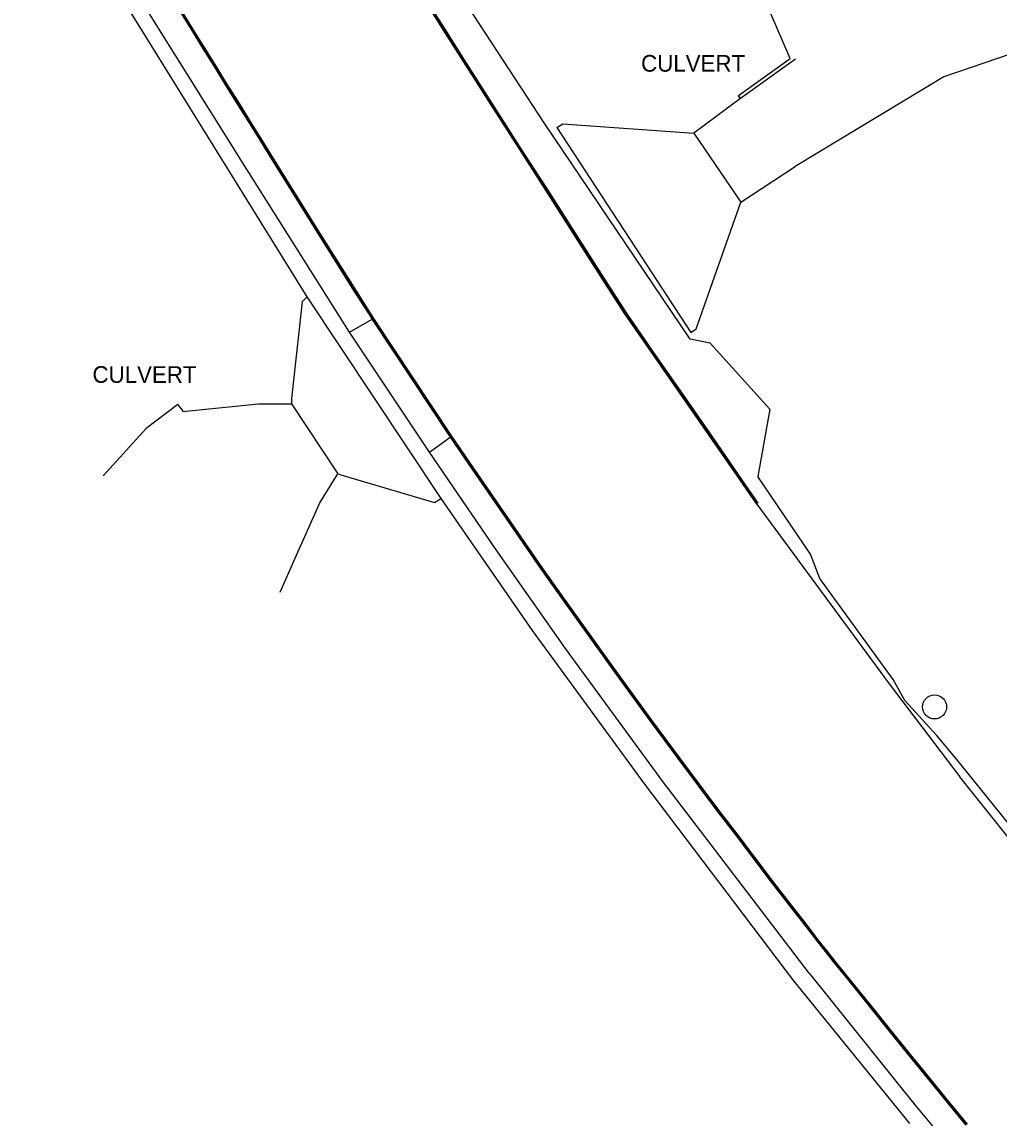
# Model space of a CAD drawing. Extents: x 368532 to 392481, y 10654822 to 10676899.
# Drawn here: x 374280.6 to 374573.7, y 10671119.3 to 10671447.9 of the extents above; entities that cross this region are included whole.
import ezdxf

# ---------------------------------------------------------------- set-up
doc = ezdxf.new("R2010")
doc.units = 0
for name, color, linetype in [('p_drainage conc drain', 7, 'Continuous'), ('p_drainage culvert', 7, 'Continuous'), ('p_dtm retaining wall', 7, 'Continuous'), ('p_dtm sidewalk', 7, 'Continuous'), ('p_road - paved curb', 7, 'Continuous'), ('p_structure constr area', 7, 'Continuous'), ('p_structure unidentified', 7, 'Continuous')]:
    doc.layers.add(name, color=color, linetype=linetype)

msp = doc.modelspace()

# ---------------------------------------------------------------- linework, layer by layer
at = {"layer": 'p_drainage conc drain'}
for p, q in [((374511, 10671437), (374496.77, 10671470.21)), ((374495.56, 10671425.88), (374511, 10671437)), ((374496.16, 10671424.98), (374495.56, 10671425.88)), ((374441.02, 10671416.31), (374442.85, 10671417.39)), ((374441.02, 10671416.31), (374481.21, 10671354.82)), ((374442.85, 10671417.39), (374482.18, 10671414.62)), ((374482.8, 10671355.94), (374496.24, 10671393.91)), ((374366.22, 10671365.53), (374364.67, 10671364.01)), ((374364.67, 10671364.01), (374361.52, 10671334.99)), ((374378.91, 10671354.92), (374385.62, 10671358.77)), ((374481.21, 10671354.82), (374482.8, 10671355.94)), ((374327.37, 10671333.18), (374317.93, 10671326.05)), ((374328.97, 10671331.27), (374327.37, 10671333.18)), ((374361.52, 10671334.99), (374361.45, 10671333.41)), ((374317.93, 10671326.05), (374304.99, 10671311.88)), ((374402.88, 10671318.95), (374409.07, 10671323.42)), ((374376.41, 10671312.02), (374375.36, 10671312.47)), ((374404.49, 10671303.69), (374376.41, 10671312.02)), ((374406.32, 10671305.01), (374404.49, 10671303.69))]:
    msp.add_line(p, q, dxfattribs=at)
at = {"layer": 'p_drainage culvert'}
for p, q in [((374496.16, 10671424.98), (374482.18, 10671414.62)), ((374482.18, 10671414.62), (374496.24, 10671393.91)), ((374496.24, 10671393.91), (374512.57, 10671404.53)), ((374328.78, 10671331.09), (374351.61, 10671333.41)), ((374351.61, 10671333.41), (374361.45, 10671333.41)), ((374361.45, 10671333.41), (374375.36, 10671312.47)), ((374369.92, 10671303.71), (374375.36, 10671312.47)), ((374362.57, 10671287.15), (374369.92, 10671303.71)), ((374358.03, 10671276.92), (374362.57, 10671287.15))]:
    msp.add_line(p, q, dxfattribs=at)
at = {"layer": 'p_dtm retaining wall'}
for p, q in [((374587.05, 10671441.71), (374557.11, 10671431.44)), ((374512.58, 10671436.71), (374496.16, 10671424.98)), ((374557.11, 10671431.44), (374512.57, 10671404.53))]:
    msp.add_line(p, q, dxfattribs=at)
at = {"layer": 'p_dtm sidewalk'}
for p, q in [((374316.79, 10671445.13), (374280.62, 10671503.52)), ((374347.52, 10671404.64), (374307.73, 10671468.42)), ((374366.22, 10671365.53), (374316.79, 10671445.13)), ((374378.91, 10671354.92), (374347.52, 10671404.64)), ((374406.32, 10671305.01), (374366.22, 10671365.53)), ((374402.88, 10671318.95), (374378.91, 10671354.92)), ((374422.66, 10671289.99), (374402.88, 10671318.95)), ((374433.78, 10671265.48), (374406.32, 10671305.01)), ((374443.66, 10671260.05), (374422.66, 10671289.99)), ((374467.47, 10671219.43), (374433.78, 10671265.48)), ((374472.79, 10671220.21), (374443.66, 10671260.05)), ((374512.09, 10671160.44), (374467.47, 10671219.43)), ((374516.71, 10671162.71), (374472.79, 10671220.21)), ((374516.71, 10671162.71), (374548.41, 10671123.22)), ((374546.87, 10671117.68), (374512.09, 10671160.44)), ((374548.41, 10671123.22), (374571.96, 10671095.17))]:
    msp.add_line(p, q, dxfattribs=at)
at = {"layer": 'p_road - paved curb'}
for p, q in [((374407.1, 10671445.46), (374402.27, 10671453.12)), ((374407.23, 10671445.54), (374402.4, 10671453.2)), ((374407.52, 10671445.73), (374402.69, 10671453.39)), ((374328.45, 10671450.3), (374331.88, 10671444.82)), ((374328.74, 10671450.48), (374332.17, 10671445)), ((374331.88, 10671444.82), (374334.81, 10671440.03)), ((374332.17, 10671445), (374335.11, 10671440.21)), ((374413.03, 10671436.08), (374407.1, 10671445.46)), ((374413.16, 10671436.16), (374407.23, 10671445.54)), ((374413.45, 10671436.35), (374407.52, 10671445.73)), ((374334.81, 10671440.03), (374338.03, 10671434.9)), ((374335.11, 10671440.21), (374338.32, 10671435.08)), ((374338.03, 10671434.9), (374341.5, 10671429.31)), ((374338.32, 10671435.08), (374341.79, 10671429.49)), ((374421.13, 10671423.41), (374413.03, 10671436.08)), ((374421.26, 10671423.49), (374413.16, 10671436.16)), ((374421.55, 10671423.68), (374413.45, 10671436.35)), ((374341.5, 10671429.31), (374344.81, 10671423.97)), ((374341.79, 10671429.49), (374345.1, 10671424.15)), ((374344.81, 10671423.97), (374348.34, 10671418.28)), ((374345.1, 10671424.15), (374348.63, 10671418.46)), ((374430.66, 10671408.54), (374421.13, 10671423.41)), ((374430.79, 10671408.62), (374421.26, 10671423.49)), ((374431.08, 10671408.81), (374421.55, 10671423.68)), ((374348.34, 10671418.28), (374351.85, 10671412.67)), ((374348.63, 10671418.46), (374352.14, 10671412.85)), ((374351.85, 10671412.67), (374354.7, 10671408.04)), ((374352.14, 10671412.85), (374355, 10671408.22)), ((374354.7, 10671408.04), (374369.02, 10671385)), ((374355, 10671408.22), (374369.31, 10671385.19)), ((374437.79, 10671397.46), (374430.66, 10671408.54)), ((374437.92, 10671397.54), (374430.79, 10671408.62)), ((374438.21, 10671397.73), (374431.08, 10671408.81)), ((374445.98, 10671384.57), (374437.79, 10671397.46)), ((374446.11, 10671384.65), (374437.92, 10671397.54)), ((374446.4, 10671384.84), (374438.21, 10671397.73)), ((374369.02, 10671385), (374380.5, 10671366.83)), ((374369.31, 10671385.19), (374380.79, 10671367.02)), ((374454.79, 10671370.83), (374445.98, 10671384.57)), ((374454.92, 10671370.91), (374446.11, 10671384.65)), ((374455.21, 10671371.1), (374446.4, 10671384.84)), ((374461.47, 10671360.41), (374454.79, 10671370.83)), ((374461.59, 10671360.49), (374454.92, 10671370.91)), ((374461.89, 10671360.69), (374455.21, 10671371.1)), ((374380.5, 10671366.83), (374385.62, 10671358.77)), ((374380.79, 10671367.02), (374385.93, 10671358.93)), ((374385.62, 10671358.77), (374385.64, 10671358.74)), ((374385.64, 10671358.74), (374409.07, 10671323.42)), ((374385.93, 10671358.93), (374409.37, 10671323.62)), ((374469.45, 10671348.89), (374461.47, 10671360.41)), ((374469.57, 10671348.98), (374461.59, 10671360.49)), ((374469.86, 10671349.17), (374461.89, 10671360.69)), ((374479.18, 10671334.88), (374469.45, 10671348.89)), ((374479.3, 10671334.97), (374469.57, 10671348.98)), ((374479.59, 10671335.17), (374469.86, 10671349.17)), ((374487.57, 10671322.79), (374479.18, 10671334.88)), ((374487.69, 10671322.88), (374479.3, 10671334.97)), ((374487.98, 10671323.08), (374479.59, 10671335.17)), ((374409.07, 10671323.42), (374409.08, 10671323.42)), ((374409.08, 10671323.42), (374415.78, 10671313.62)), ((374409.37, 10671323.62), (374416.07, 10671313.82)), ((374495.04, 10671312.03), (374487.57, 10671322.79)), ((374495.16, 10671312.12), (374487.69, 10671322.88)), ((374495.45, 10671312.32), (374487.98, 10671323.08)), ((374415.78, 10671313.62), (374421.53, 10671305.28)), ((374416.07, 10671313.82), (374421.82, 10671305.47)), ((374501.05, 10671303.38), (374495.04, 10671312.03)), ((374501.17, 10671303.47), (374495.16, 10671312.12)), ((374501.46, 10671303.67), (374495.45, 10671312.32)), ((374421.53, 10671305.28), (374436.17, 10671284.03)), ((374421.82, 10671305.47), (374436.46, 10671284.23)), ((374501.05, 10671303.38), (374540.97, 10671249.08)), ((374436.17, 10671284.03), (374441.76, 10671276.12)), ((374436.46, 10671284.23), (374442.05, 10671276.32)), ((374441.76, 10671276.12), (374452.35, 10671261.37)), ((374442.05, 10671276.32), (374452.64, 10671261.57)), ((374452.35, 10671261.37), (374458.96, 10671252.18)), ((374452.64, 10671261.57), (374459.25, 10671252.38)), ((374458.96, 10671252.18), (374465.08, 10671243.75)), ((374459.25, 10671252.38), (374465.36, 10671243.95)), ((374540.97, 10671249.08), (374561.88, 10671221.56)), ((374465.08, 10671243.75), (374469.05, 10671238.26)), ((374465.36, 10671243.95), (374469.33, 10671238.47)), ((374469.05, 10671238.26), (374477.29, 10671227.09)), ((374469.33, 10671238.47), (374477.57, 10671227.3)), ((374477.57, 10671227.3), (374489.75, 10671211.11)), ((374477.29, 10671227.09), (374489.47, 10671210.9)), ((374589.65, 10671186.84), (374561.88, 10671221.56)), ((374489.47, 10671210.9), (374494.59, 10671204.15)), ((374489.75, 10671211.11), (374494.87, 10671204.36)), ((374494.87, 10671204.36), (374499.52, 10671198.27)), ((374494.59, 10671204.15), (374499.24, 10671198.06)), ((374499.24, 10671198.06), (374505.06, 10671190.38)), ((374499.52, 10671198.27), (374505.34, 10671190.59)), ((374505.06, 10671190.38), (374511.27, 10671182.38)), ((374505.34, 10671190.59), (374511.55, 10671182.6)), ((374511.27, 10671182.38), (374514.59, 10671178.09)), ((374511.55, 10671182.6), (374514.87, 10671178.31)), ((374514.59, 10671178.09), (374519.27, 10671172.03)), ((374514.87, 10671178.31), (374519.54, 10671172.25)), ((374519.27, 10671172.03), (374521.49, 10671169.19)), ((374519.54, 10671172.25), (374521.76, 10671169.41)), ((374521.49, 10671169.19), (374524.05, 10671166.05)), ((374521.76, 10671169.41), (374524.32, 10671166.27)), ((374524.05, 10671166.05), (374527.77, 10671161.42)), ((374524.32, 10671166.27), (374528.04, 10671161.64)), ((374528.04, 10671161.64), (374534.6, 10671153.53)), ((374527.77, 10671161.42), (374534.33, 10671153.31)), ((374534.33, 10671153.31), (374539.93, 10671146.33)), ((374534.6, 10671153.53), (374540.2, 10671146.55)), ((374539.93, 10671146.33), (374546.61, 10671138.06)), ((374540.2, 10671146.55), (374546.88, 10671138.28)), ((374546.61, 10671138.06), (374552.88, 10671130.31)), ((374546.88, 10671138.28), (374553.15, 10671130.54)), ((374552.88, 10671130.31), (374558.49, 10671123.45)), ((374553.15, 10671130.54), (374558.76, 10671123.67)), ((374558.49, 10671123.45), (374563.71, 10671117.13)), ((374558.76, 10671123.67), (374563.98, 10671117.35))]:
    msp.add_line(p, q, dxfattribs=at)
msp.add_lwpolyline([(374328.87, 10671450.56), (374332.3, 10671445.08), (374335.24, 10671440.29), (374338.45, 10671435.16), (374341.92, 10671429.57), (374345.23, 10671424.23), (374348.76, 10671418.54), (374352.27, 10671412.93), (374355.13, 10671408.3), (374369.44, 10671385.27), (374380.92, 10671367.1), (374386.06, 10671359.01), (374409.49, 10671323.7), (374416.19, 10671313.9), (374421.94, 10671305.56), (374436.58, 10671284.32), (374442.17, 10671276.41), (374452.76, 10671261.66), (374459.37, 10671252.47), (374465.48, 10671244.04), (374469.45, 10671238.56), (374477.69, 10671227.39), (374489.87, 10671211.2), (374494.99, 10671204.45), (374499.64, 10671198.36), (374505.46, 10671190.68), (374511.67, 10671182.69), (374514.99, 10671178.4), (374519.66, 10671172.34), (374521.88, 10671169.5), (374524.44, 10671166.36), (374528.16, 10671161.73), (374534.72, 10671153.62), (374540.32, 10671146.64), (374547, 10671138.37), (374553.27, 10671130.63), (374558.88, 10671123.77), (374564.1, 10671117.45)], dxfattribs=at)
at = {"layer": 'p_structure constr area'}
for p, q in [((374437.23, 10671417.71), (374320.47, 10671596.53)), ((374481.03, 10671352.8), (374437.23, 10671417.71)), ((374487.05, 10671351.63), (374481.03, 10671352.8)), ((374504.96, 10671331.79), (374487.05, 10671351.63)), ((374504.96, 10671331.79), (374501.34, 10671311.68)), ((374517.12, 10671288.31), (374501.34, 10671311.68)), ((374519.92, 10671281.03), (374517.12, 10671288.31)), ((374541.93, 10671250.78), (374519.92, 10671281.03)), ((374545.4, 10671244.51), (374541.93, 10671250.78)), ((374554.9, 10671234.11), (374545.4, 10671244.51)), ((374561.04, 10671226.8), (374554.9, 10671234.11)), ((374588.36, 10671192.75), (374561.04, 10671226.8))]:
    msp.add_line(p, q, dxfattribs=at)
at = {"layer": 'p_structure unidentified'}
msp.add_circle((374554.32, 10671242.55), 3.62, dxfattribs=at)

# ---------------------------------------------------------------- texts
at = {"layer": 'p_drainage culvert'}
for p in [(374464.46, 10671433.01), (374299.93, 10671339.71)]:
    msp.add_text(' CULVERT', height=5, dxfattribs=at).set_placement(p)

doc.saveas('drawing.dxf')
